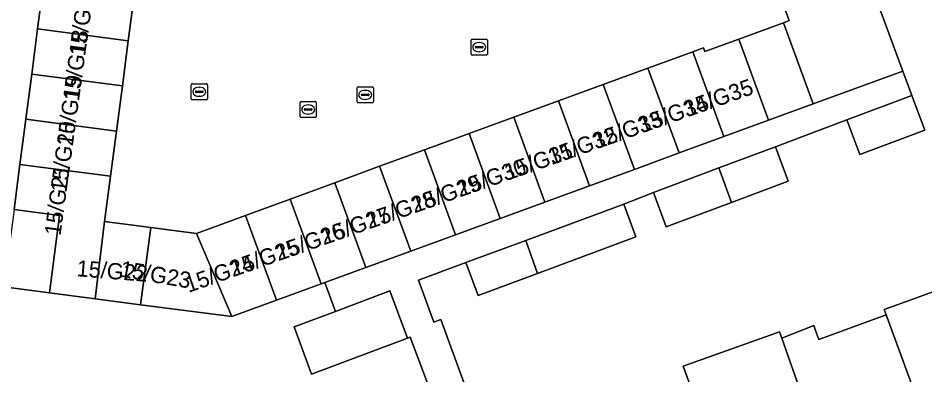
# Model space of a CAD drawing. Extents: x 161258 to 161838, y 380833 to 381727.
# Drawn here: x 161606.8 to 161662.6, y 381501.6 to 381523.6 of the extents above; entities that cross this region are included whole.
import ezdxf

# ---------------------------------------------------------------- set-up
doc = ezdxf.new("R2010")
doc.units = 0
for name, color, linetype in [('IMGEO_Erf', 7, 'Continuous'), ('IMGEO_Kolk', 7, 'Continuous'), ('IMGEO_Pand', 7, 'Continuous'), ('IMGEO_Pand_nummerreeks', 7, 'Continuous'), ('IMGEO_Rijbaan_lokaal_open', 7, 'Continuous'), ('IMGEO_Rioolput', 7, 'Continuous'), ('IMGEO_Voetpad_open', 7, 'Continuous')]:
    doc.layers.add(name, color=color, linetype=linetype)

msp = doc.modelspace()

# ---------------------------------------------------------------- linework, layer by layer
at = {"layer": 'IMGEO_Erf'}
for points in [[(161658.502, 381527.949), (161661.283, 381520.357), (161661.849, 381518.849), (161662.646, 381516.724), (161658.643, 381515.224), (161657.846, 381517.349), (161656.102, 381516.695), (161653.448, 381515.7), (161654.227, 381513.569), (161650.728, 381512.257), (161646.713, 381510.753), (161645.917, 381512.877), (161644.091, 381512.159), (161644.843, 381510.13), (161638.785, 381507.883), (161635.114, 381506.522), (161634.362, 381508.551), (161631.436, 381507.466), (161632.385, 381504.866), (161632.83, 381505.029), (161635.789, 381496.926)], [(161606.522, 381511.821), (161606.886, 381514.607), (161607.25, 381517.392), (161607.615, 381520.177), (161607.979, 381522.962), (161608.344, 381525.748)], [(161649.21, 381498.143), (161647.757, 381502.15), (161653.689, 381504.271), (161653.824, 381503.89), (161655.799, 381504.662), (161655.909, 381504.366), (161655.996, 381504.132), (161656.119, 381503.802), (161660.262, 381505.316), (161660.141, 381505.647), (161661.968, 381506.314), (161662.13, 381506.373), (161666.051, 381507.805)], [(161633.723, 381496.514), (161630.927, 381503.955), (161630.765, 381503.894), (161624.844, 381501.669), (161623.779, 381504.583), (161626.323, 381505.539), (161625.673, 381507.315), (161625.454, 381507.235), (161622.698, 381506.225), (161619.942, 381505.216), (161614.324, 381505.951), (161611.516, 381506.318), (161608.707, 381506.686), (161605.898, 381507.053)]]:
    msp.add_lwpolyline(points, dxfattribs=at)
at = {"layer": 'IMGEO_Kolk'}
for p, q in [((161634.761, 381522.339), (161635.613, 381522.339)), ((161634.686, 381521.413), (161634.686, 381522.265)), ((161634.945, 381521.833), (161634.945, 381521.845)), ((161635.383, 381521.796), (161634.985, 381521.796)), ((161634.988, 381521.882), (161635.386, 381521.882)), ((161635.174, 381522.119), (161635.199, 381522.119)), ((161635.429, 381521.845), (161635.429, 381521.833)), ((161635.687, 381522.265), (161635.687, 381521.413)), ((161635.613, 381521.339), (161634.761, 381521.339)), ((161635.197, 381521.559), (161635.172, 381521.559)), ((161617.514, 381519.587), (161618.366, 381519.587)), ((161617.439, 381518.661), (161617.439, 381519.513)), ((161617.698, 381519.081), (161617.698, 381519.093)), ((161618.136, 381519.044), (161617.738, 381519.044)), ((161617.741, 381519.13), (161618.139, 381519.13)), ((161617.927, 381519.367), (161617.952, 381519.367)), ((161618.182, 381519.093), (161618.182, 381519.081)), ((161618.44, 381519.513), (161618.44, 381518.661)), ((161618.366, 381518.587), (161617.514, 381518.587)), ((161617.95, 381518.807), (161617.925, 381518.807)), ((161624.149, 381517.566), (161624.149, 381518.418)), ((161624.224, 381518.492), (161625.076, 381518.492)), ((161625.15, 381518.418), (161625.15, 381517.566)), ((161624.408, 381517.986), (161624.408, 381517.998)), ((161624.846, 381517.949), (161624.448, 381517.949)), ((161624.451, 381518.035), (161624.849, 381518.035)), ((161624.637, 381518.272), (161624.662, 381518.272)), ((161624.892, 381517.998), (161624.892, 381517.986)), ((161625.076, 381517.492), (161624.224, 381517.492)), ((161624.66, 381517.712), (161624.635, 381517.712))]:
    msp.add_line(p, q, dxfattribs=at)
for points in [[(161634.761, 381522.339), (161635.613, 381522.339)], [(161634.686, 381521.413), (161634.686, 381522.265)], [(161635.687, 381522.265), (161635.687, 381521.413)], [(161635.613, 381521.339), (161634.761, 381521.339)], [(161617.514, 381519.587), (161618.366, 381519.587)], [(161617.439, 381518.661), (161617.439, 381519.513)], [(161618.44, 381519.513), (161618.44, 381518.661)], [(161618.366, 381518.587), (161617.514, 381518.587)], [(161624.149, 381517.566), (161624.149, 381518.418)], [(161624.224, 381518.492), (161625.076, 381518.492)], [(161625.15, 381518.418), (161625.15, 381517.566)], [(161625.076, 381517.492), (161624.224, 381517.492)]]:
    msp.add_lwpolyline(points, dxfattribs=at)
for centre, radius, start, end in [((161634.763, 381522.263), 0.0765, 91.552, 178.448), ((161634.763, 381522.263), 0.0765, 91.552, 178.448), ((161635.611, 381522.263), 0.0765, 1.552, 88.448), ((161635.611, 381522.263), 0.0765, 1.552, 88.448), ((161634.985, 381521.842), 0.0403, 85.8775, 175.7526), ((161634.982, 381521.832), 0.0366, 178.938, 274.7102), ((161635.386, 381521.839), 0.043, 264.8664, 352.4533), ((161635.39, 381521.844), 0.0386, 1.7309, 96.639), ((161634.763, 381521.415), 0.0765, 181.552, 268.448), ((161634.763, 381521.415), 0.0765, 181.552, 268.448), ((161635.611, 381521.415), 0.0765, 271.552, 358.448), ((161635.611, 381521.415), 0.0765, 271.552, 358.448), ((161617.516, 381519.511), 0.0765, 91.552, 178.448), ((161617.516, 381519.511), 0.0765, 91.552, 178.448), ((161618.364, 381519.511), 0.0765, 1.552, 88.448), ((161618.364, 381519.511), 0.0765, 1.552, 88.448), ((161617.738, 381519.09), 0.0403, 85.8775, 175.7526), ((161617.735, 381519.08), 0.0366, 178.938, 274.7102), ((161618.139, 381519.087), 0.043, 264.8664, 352.4533), ((161618.143, 381519.092), 0.0386, 1.7309, 96.639), ((161617.516, 381518.663), 0.0765, 181.552, 268.448), ((161617.516, 381518.663), 0.0765, 181.552, 268.448), ((161618.364, 381518.663), 0.0765, 271.552, 358.448), ((161618.364, 381518.663), 0.0765, 271.552, 358.448), ((161624.226, 381518.416), 0.0765, 91.552, 178.448), ((161624.226, 381518.416), 0.0765, 91.552, 178.448), ((161625.074, 381518.416), 0.0765, 1.552, 88.448), ((161625.074, 381518.416), 0.0765, 1.552, 88.448), ((161624.448, 381517.995), 0.0403, 85.8775, 175.7526), ((161624.445, 381517.985), 0.0366, 178.938, 274.7102), ((161624.849, 381517.992), 0.043, 264.8664, 352.4533), ((161624.853, 381517.997), 0.0386, 1.7309, 96.639), ((161624.226, 381517.568), 0.0765, 181.552, 268.448), ((161624.226, 381517.568), 0.0765, 181.552, 268.448), ((161625.074, 381517.568), 0.0765, 271.552, 358.448), ((161625.074, 381517.568), 0.0765, 271.552, 358.448)]:
    msp.add_arc(centre, radius, start, end, dxfattribs=at)
for centre, major_axis, ratio, start_param, end_param in [((161635.173, 381521.839), (-0.387, 0.002), 0.722429, 4.712389, 7.853982), ((161635.198, 381521.839), (-0.39, 0.002), 0.717154, 1.570796, 4.712389), ((161617.926, 381519.087), (-0.387, 0.002), 0.722429, 4.712389, 7.853982), ((161617.951, 381519.087), (-0.39, 0.002), 0.717154, 1.570796, 4.712389), ((161624.636, 381517.992), (-0.387, 0.002), 0.722429, 4.712389, 7.853982), ((161624.661, 381517.992), (-0.39, 0.002), 0.717154, 1.570796, 4.712389)]:
    msp.add_ellipse(centre, major_axis=major_axis, ratio=ratio, start_param=start_param, end_param=end_param, dxfattribs=at)
at = {"layer": 'IMGEO_Pand'}
for points in [[(161653.937, 381523.345), (161655.771, 381518.338), (161661.283, 381520.357), (161658.502, 381527.949), (161653.346, 381526.061), (161654.293, 381523.475)], [(161607.979, 381522.962), (161613.562, 381522.232), (161613.926, 381525.017), (161608.344, 381525.748)], [(161607.979, 381522.962), (161607.615, 381520.177), (161613.198, 381519.447), (161613.562, 381522.232)], [(161653.937, 381523.345), (161651.181, 381522.335), (161653.015, 381517.329), (161655.771, 381518.338)], [(161653.015, 381517.329), (161651.181, 381522.335), (161649.086, 381521.568), (161649.002, 381521.795), (161648.342, 381521.553), (161650.259, 381516.319)], [(161647.503, 381515.31), (161650.259, 381516.319), (161648.342, 381521.553), (161645.586, 381520.544)], [(161613.198, 381519.447), (161607.615, 381520.177), (161607.25, 381517.392), (161612.834, 381516.662)], [(161647.503, 381515.31), (161645.586, 381520.544), (161642.83, 381519.534), (161644.747, 381514.301)], [(161644.747, 381514.301), (161642.83, 381519.534), (161640.074, 381518.525), (161641.991, 381513.291)], [(161637.318, 381517.516), (161639.234, 381512.282), (161641.991, 381513.291), (161640.074, 381518.525)], [(161661.849, 381518.849), (161657.846, 381517.349), (161658.643, 381515.224), (161662.646, 381516.724)], [(161612.469, 381513.876), (161612.834, 381516.662), (161607.25, 381517.392), (161606.886, 381514.607)], [(161637.318, 381517.516), (161634.561, 381516.506), (161636.478, 381511.272), (161639.234, 381512.282)], [(161634.561, 381516.506), (161631.805, 381515.497), (161633.722, 381510.263), (161636.478, 381511.272)], [(161653.448, 381515.7), (161649.951, 381514.389), (161650.728, 381512.257), (161654.227, 381513.569)], [(161630.966, 381509.254), (161633.722, 381510.263), (161631.805, 381515.497), (161629.049, 381514.488)], [(161608.707, 381506.686), (161611.516, 381506.318), (161612.105, 381511.091), (161612.469, 381513.876), (161606.886, 381514.607), (161606.522, 381511.821), (161609.331, 381511.454)], [(161628.21, 381508.244), (161630.966, 381509.254), (161629.049, 381514.488), (161626.293, 381513.478)], [(161650.728, 381512.257), (161649.951, 381514.389), (161645.917, 381512.877), (161646.713, 381510.753)], [(161626.293, 381513.478), (161623.537, 381512.469), (161625.454, 381507.235), (161625.673, 381507.315), (161628.21, 381508.244)], [(161620.781, 381511.46), (161622.698, 381506.225), (161625.454, 381507.235), (161623.537, 381512.469)], [(161608.707, 381506.686), (161609.331, 381511.454), (161606.522, 381511.821), (161605.898, 381507.053)], [(161638.052, 381509.919), (161638.785, 381507.883), (161644.843, 381510.13), (161644.091, 381512.159)], [(161617.757, 381510.352), (161619.942, 381505.216), (161622.698, 381506.225), (161620.781, 381511.46)], [(161612.105, 381511.091), (161611.516, 381506.318), (161614.324, 381505.951), (161614.948, 381510.719)], [(161617.757, 381510.352), (161614.948, 381510.719), (161614.324, 381505.951), (161619.942, 381505.216)], [(161638.052, 381509.919), (161634.362, 381508.551), (161635.114, 381506.522), (161638.785, 381507.883)], [(161666.051, 381507.805), (161662.13, 381506.373), (161661.968, 381506.314), (161660.141, 381505.647), (161660.262, 381505.316), (161662.204, 381500), (161664.137, 381494.711), (161670.084, 381496.883), (161668.918, 381500)], [(161626.323, 381505.539), (161623.779, 381504.583), (161624.844, 381501.669), (161630.765, 381503.894), (161629.674, 381506.798)], [(161660.262, 381505.316), (161656.119, 381503.802), (161655.996, 381504.132), (161655.909, 381504.366), (161655.799, 381504.662), (161653.824, 381503.89), (161655.082, 381500.309), (161655.194, 381500), (161657.945, 381492.45), (161664.137, 381494.711), (161662.204, 381500)], [(161655.194, 381500), (161655.082, 381500.309), (161653.824, 381503.89), (161653.689, 381504.271), (161647.757, 381502.15), (161649.21, 381498.143), (161652.072, 381490.305), (161657.945, 381492.45)]]:
    msp.add_lwpolyline(points, close=True, dxfattribs=at)
at = {"layer": 'IMGEO_Rijbaan_lokaal_open'}
msp.add_lwpolyline([(161613.926, 381525.017), (161613.562, 381522.232), (161613.198, 381519.447), (161612.834, 381516.662), (161612.469, 381513.876), (161612.105, 381511.091), (161614.948, 381510.719), (161617.757, 381510.352), (161620.781, 381511.46), (161623.537, 381512.469), (161626.293, 381513.478), (161629.049, 381514.488), (161631.805, 381515.497), (161634.561, 381516.506), (161637.318, 381517.516), (161640.074, 381518.525), (161642.83, 381519.534), (161645.586, 381520.544), (161648.342, 381521.553), (161649.002, 381521.795), (161649.086, 381521.568), (161651.181, 381522.335), (161653.937, 381523.345), (161654.293, 381523.475), (161653.346, 381526.061)], dxfattribs=at)
at = {"layer": 'IMGEO_Rioolput'}
for p, q in [((161627.662, 381518.469), (161627.662, 381519.321)), ((161627.737, 381519.395), (161628.589, 381519.395)), ((161628.15, 381519.175), (161628.175, 381519.175)), ((161628.663, 381519.321), (161628.663, 381518.469)), ((161627.921, 381518.889), (161627.921, 381518.901)), ((161628.359, 381518.852), (161627.961, 381518.852)), ((161627.964, 381518.938), (161628.362, 381518.938)), ((161628.173, 381518.615), (161628.148, 381518.615)), ((161628.405, 381518.901), (161628.405, 381518.889)), ((161628.589, 381518.395), (161627.737, 381518.395))]:
    msp.add_line(p, q, dxfattribs=at)
for points in [[(161627.662, 381518.469), (161627.662, 381519.321)], [(161627.737, 381519.395), (161628.589, 381519.395)], [(161628.663, 381519.321), (161628.663, 381518.469)], [(161628.589, 381518.395), (161627.737, 381518.395)]]:
    msp.add_lwpolyline(points, dxfattribs=at)
for centre, radius, start, end in [((161627.739, 381519.319), 0.0765, 91.552, 178.448), ((161627.739, 381519.319), 0.0765, 91.552, 178.448), ((161628.587, 381519.319), 0.0765, 1.552, 88.448), ((161628.587, 381519.319), 0.0765, 1.552, 88.448), ((161627.739, 381518.471), 0.0765, 181.552, 268.448), ((161627.739, 381518.471), 0.0765, 181.552, 268.448), ((161627.961, 381518.898), 0.0403, 85.8775, 175.7526), ((161627.958, 381518.888), 0.0366, 178.938, 274.7102), ((161628.362, 381518.895), 0.043, 264.8664, 352.4533), ((161628.366, 381518.9), 0.0386, 1.7309, 96.639), ((161628.587, 381518.471), 0.0765, 271.552, 358.448), ((161628.587, 381518.471), 0.0765, 271.552, 358.448)]:
    msp.add_arc(centre, radius, start, end, dxfattribs=at)
for centre, major_axis, ratio, start_param, end_param in [((161628.149, 381518.895), (-0.387, 0.002), 0.722429, 4.712389, 7.853982), ((161628.174, 381518.895), (-0.39, 0.002), 0.717154, 1.570796, 4.712389)]:
    msp.add_ellipse(centre, major_axis=major_axis, ratio=ratio, start_param=start_param, end_param=end_param, dxfattribs=at)
at = {"layer": 'IMGEO_Voetpad_open'}
msp.add_lwpolyline([(161635.789, 381496.926), (161632.83, 381505.029), (161632.385, 381504.866), (161631.436, 381507.466), (161634.362, 381508.551), (161638.052, 381509.919), (161644.091, 381512.159), (161645.917, 381512.877), (161649.951, 381514.389), (161653.448, 381515.7), (161656.102, 381516.695), (161657.846, 381517.349), (161661.849, 381518.849), (161661.283, 381520.357), (161655.771, 381518.338), (161653.015, 381517.329), (161650.259, 381516.319), (161647.503, 381515.31), (161644.747, 381514.301), (161641.991, 381513.291), (161639.234, 381512.282), (161636.478, 381511.272), (161633.722, 381510.263), (161630.966, 381509.254), (161628.21, 381508.244), (161625.673, 381507.315), (161626.323, 381505.539), (161629.674, 381506.798), (161630.765, 381503.894), (161630.927, 381503.955), (161633.723, 381496.514)], dxfattribs=at)

# ---------------------------------------------------------------- texts
at = {"layer": 'IMGEO_Pand_nummerreeks'}
for s, rotation, p in [('15/G17', 82.2143, (161610.898, 381521.255)), ('15/G18', 82.2143, (161610.519, 381518.482)), ('15/G19', 82.2143, (161610.139, 381515.701)), ('15/G35', 19.4143, (161648.032, 381517.519)), ('15/G34', 19.4143, (161645.236, 381516.534)), ('15/G33', 19.4143, (161642.439, 381515.548)), ('15/G20', 82.2143, (161609.748, 381512.841)), ('15/G32', 19.4143, (161639.637, 381514.561)), ('15/G31', 19.4143, (161636.95, 381513.614)), ('15/G30', 19.4143, (161634.053, 381512.593)), ('15/G21', 82.2143, (161609.383, 381510.172)), ('15/G29', 19.4143, (161631.251, 381511.605)), ('15/G28', 19.4143, (161628.46, 381510.621)), ('15/G27', 19.4143, (161625.661, 381509.635)), ('15/G26', 19.4118, (161622.864, 381508.65)), ('15/G25', 19.4143, (161620.068, 381507.664)), ('15/G24', 19.4143, (161617.271, 381506.678)), ('15/G22', 355.4261, (161610.351, 381507.709)), ('15/G23', 350.1342, (161613.007, 381507.696))]:
    msp.add_text(s, height=1, rotation=rotation, dxfattribs=at).set_placement(p)

doc.saveas('drawing.dxf')
